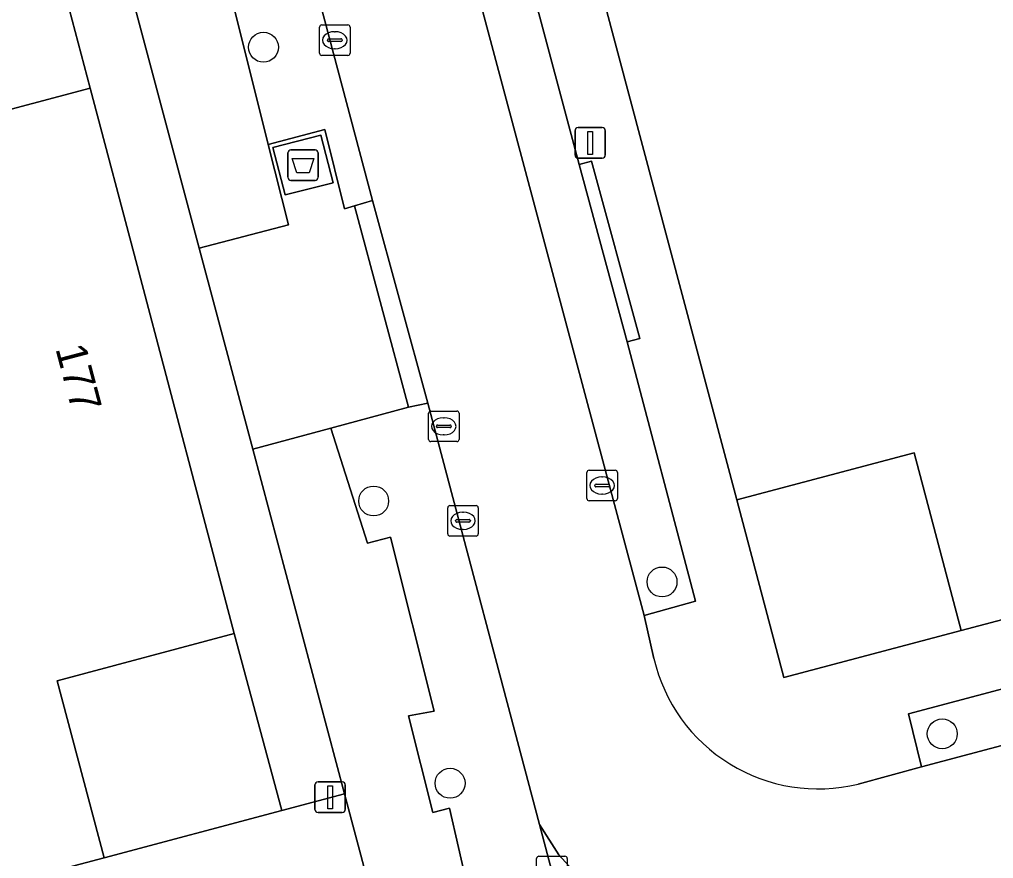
# Model space of a CAD drawing. Extents: x 162542 to 163147, y 380779 to 381521.
# Drawn here: x 162637.43 to 162669.28, y 381104.34 to 381131.79 of the extents above; entities that cross this region are included whole.
import ezdxf

# ---------------------------------------------------------------- set-up
doc = ezdxf.new("R2010")
doc.units = 0
for name, color, linetype in [('IMGEO_Afval_apart_plaats', 7, 'Continuous'), ('IMGEO_Boom', 7, 'Continuous'), ('IMGEO_Erf', 7, 'Continuous'), ('IMGEO_Groenvoorziening', 7, 'Continuous'), ('IMGEO_Kolk', 7, 'Continuous'), ('IMGEO_Lichtmast', 7, 'Continuous'), ('IMGEO_Muur', 7, 'Continuous'), ('IMGEO_Pand', 7, 'Continuous'), ('IMGEO_Pand_nummerreeks', 7, 'Continuous'), ('IMGEO_Parkeervlak_open', 7, 'Continuous'), ('IMGEO_Rijbaan_lokaal_open', 7, 'Continuous'), ('IMGEO_Rioolput', 7, 'Continuous'), ('IMGEO_Voetpad_gesloten', 7, 'Continuous'), ('IMGEO_Voetpad_open', 7, 'Continuous')]:
    doc.layers.add(name, color=color, linetype=linetype)

msp = doc.modelspace()

# ---------------------------------------------------------------- linework, layer by layer
at = {"layer": 'IMGEO_Afval_apart_plaats'}
for p, q in [((162646.209, 381126.625), (162646.209, 381127.425)), ((162646.209, 381127.425), (162646.209, 381126.625)), ((162646.309, 381127.525), (162647.099, 381127.525)), ((162647.099, 381127.525), (162646.309, 381127.525)), ((162647.199, 381127.425), (162647.199, 381126.625)), ((162647.199, 381126.625), (162647.199, 381127.425)), ((162647.099, 381126.525), (162646.309, 381126.525)), ((162646.309, 381126.525), (162647.099, 381126.525))]:
    msp.add_line(p, q, dxfattribs=at)
msp.add_lwpolyline([(162646.352, 381127.239), (162647.056, 381127.239), (162646.907, 381126.769), (162646.501, 381126.769), (162646.352, 381127.239)], dxfattribs=at)
for centre, start, end in [((162646.309, 381127.425), 90, 180), ((162646.309, 381127.425), 90, 180), ((162647.099, 381127.425), 0, 90), ((162647.099, 381127.425), 360, 90), ((162646.309, 381126.625), 180, 270), ((162646.309, 381126.625), 180, 270), ((162647.099, 381126.625), 270, 0), ((162647.099, 381126.625), 270, 0)]:
    msp.add_arc(centre, 0.1, start, end, dxfattribs=at)
at = {"layer": 'IMGEO_Boom'}
for centre in [(162645.411, 381130.88), (162649.015, 381116.036), (162658.444, 381113.388), (162667.608, 381108.419), (162651.513, 381106.802)]:
    msp.add_circle(centre, 0.489, dxfattribs=at)
at = {"layer": 'IMGEO_Erf'}
for points in [[(162639.746, 381129.54), (162636.792, 381140.677), (162633.868, 381139.932), (162635.326, 381134.447), (162636.835, 381128.769)], [(162662.432, 381110.26), (162668.23, 381111.802), (162666.685, 381117.612), (162660.887, 381116.07)], [(162646.014, 381105.912), (162644.458, 381111.704), (162638.664, 381110.158), (162640.197, 381104.368)]]:
    msp.add_lwpolyline(points, close=True, dxfattribs=at)
at = {"layer": 'IMGEO_Groenvoorziening'}
for points in [[(162646.141, 381136.563), (162644.655, 381136.184), (162645.512, 381132.926), (162644.373, 381132.48), (162645.568, 381127.699), (162647.414, 381128.192), (162648.065, 381125.594), (162648.385, 381125.691), (162648.974, 381125.871)], [(162644.655, 381136.184), (162640.435, 381135.109), (162643.311, 381124.312), (162646.229, 381125.075), (162645.568, 381127.699), (162644.373, 381132.48), (162645.512, 381132.926)], [(162650.784, 381119.239), (162650.158, 381119.106), (162647.612, 381118.42), (162648.817, 381114.655), (162649.56, 381114.853), (162650.996, 381109.159), (162650.154, 381109.01), (162650.946, 381105.841), (162651.491, 381105.99), (162652.085, 381103.415), (162653.175, 381103.613), (162653.617, 381101.793), (162655.29, 381102.237), (162654.437, 381105.453)], [(162649.56, 381114.853), (162648.817, 381114.655), (162647.612, 381118.42), (162645.063, 381117.734), (162648.066, 381106.457), (162649.592, 381100.726), (162653.617, 381101.793), (162653.175, 381103.613), (162652.085, 381103.415), (162651.491, 381105.99), (162650.946, 381105.841), (162650.154, 381109.01), (162650.996, 381109.159)]]:
    msp.add_lwpolyline(points, close=True, dxfattribs=at)
at = {"layer": 'IMGEO_Kolk'}
for p, q in [((162647.319, 381131.61), (162648.171, 381131.61)), ((162647.244, 381130.684), (162647.244, 381131.536)), ((162647.732, 381131.39), (162647.757, 381131.39)), ((162648.245, 381131.536), (162648.245, 381130.684)), ((162647.503, 381131.104), (162647.503, 381131.116)), ((162647.941, 381131.067), (162647.543, 381131.067)), ((162647.546, 381131.153), (162647.944, 381131.153)), ((162647.987, 381131.116), (162647.987, 381131.104)), ((162648.171, 381130.61), (162647.319, 381130.61)), ((162647.755, 381130.83), (162647.73, 381130.83)), ((162655.986, 381116.118), (162655.986, 381116.97)), ((162656.061, 381117.044), (162656.913, 381117.044)), ((162656.987, 381116.97), (162656.987, 381116.118)), ((162656.288, 381116.587), (162656.686, 381116.587)), ((162656.474, 381116.824), (162656.499, 381116.824)), ((162656.245, 381116.538), (162656.245, 381116.55)), ((162656.683, 381116.501), (162656.285, 381116.501)), ((162656.497, 381116.264), (162656.472, 381116.264)), ((162656.729, 381116.55), (162656.729, 381116.538)), ((162656.913, 381116.044), (162656.061, 381116.044)), ((162651.435, 381114.963), (162651.435, 381115.815)), ((162651.51, 381115.889), (162652.362, 381115.889)), ((162651.923, 381115.669), (162651.948, 381115.669)), ((162652.436, 381115.815), (162652.436, 381114.963)), ((162651.694, 381115.383), (162651.694, 381115.395)), ((162652.132, 381115.346), (162651.734, 381115.346)), ((162651.737, 381115.432), (162652.135, 381115.432)), ((162652.178, 381115.395), (162652.178, 381115.383)), ((162651.946, 381115.109), (162651.921, 381115.109)), ((162652.362, 381114.889), (162651.51, 381114.889)), ((162654.344, 381103.488), (162654.344, 381104.34)), ((162654.419, 381104.414), (162655.271, 381104.414)), ((162655.345, 381104.34), (162655.345, 381103.488))]:
    msp.add_line(p, q, dxfattribs=at)
for points in [[(162647.319, 381131.61), (162648.171, 381131.61)], [(162647.244, 381130.684), (162647.244, 381131.536)], [(162648.245, 381131.536), (162648.245, 381130.684)], [(162648.171, 381130.61), (162647.319, 381130.61)], [(162655.986, 381116.118), (162655.986, 381116.97)], [(162656.061, 381117.044), (162656.913, 381117.044)], [(162656.987, 381116.97), (162656.987, 381116.118)], [(162656.913, 381116.044), (162656.061, 381116.044)], [(162651.435, 381114.963), (162651.435, 381115.815)], [(162651.51, 381115.889), (162652.362, 381115.889)], [(162652.436, 381115.815), (162652.436, 381114.963)], [(162652.362, 381114.889), (162651.51, 381114.889)], [(162654.344, 381103.488), (162654.344, 381104.34)], [(162654.419, 381104.414), (162655.271, 381104.414)], [(162655.345, 381104.34), (162655.345, 381103.488)]]:
    msp.add_lwpolyline(points, dxfattribs=at)
for centre, radius, start, end in [((162647.321, 381131.534), 0.0765, 91.552, 178.448), ((162647.321, 381131.534), 0.0765, 91.552, 178.448), ((162648.169, 381131.534), 0.0765, 1.552, 88.448), ((162648.169, 381131.534), 0.0765, 1.552, 88.448), ((162647.543, 381131.113), 0.0403, 85.8775, 175.7526), ((162647.54, 381131.103), 0.0366, 178.938, 274.7102), ((162647.944, 381131.11), 0.043, 264.8664, 352.4533), ((162647.948, 381131.115), 0.0386, 1.7309, 96.639), ((162647.321, 381130.686), 0.0765, 181.552, 268.448), ((162647.321, 381130.686), 0.0765, 181.552, 268.448), ((162648.169, 381130.686), 0.0765, 271.552, 358.448), ((162648.169, 381130.686), 0.0765, 271.552, 358.448), ((162656.063, 381116.968), 0.0765, 91.552, 178.448), ((162656.063, 381116.968), 0.0765, 91.552, 178.448), ((162656.911, 381116.968), 0.0765, 1.552, 88.448), ((162656.911, 381116.968), 0.0765, 1.552, 88.448), ((162656.285, 381116.547), 0.0403, 85.8775, 175.7526), ((162656.69, 381116.549), 0.0386, 1.7309, 96.639), ((162656.282, 381116.537), 0.0366, 178.938, 274.7102), ((162656.686, 381116.544), 0.043, 264.8664, 352.4533), ((162656.063, 381116.12), 0.0765, 181.552, 268.448), ((162656.063, 381116.12), 0.0765, 181.552, 268.448), ((162656.911, 381116.12), 0.0765, 271.552, 358.448), ((162656.911, 381116.12), 0.0765, 271.552, 358.448), ((162651.512, 381115.813), 0.0765, 91.552, 178.448), ((162651.512, 381115.813), 0.0765, 91.552, 178.448), ((162652.36, 381115.813), 0.0765, 1.552, 88.448), ((162652.36, 381115.813), 0.0765, 1.552, 88.448), ((162651.734, 381115.392), 0.0403, 85.8775, 175.7526), ((162651.731, 381115.382), 0.0366, 178.938, 274.7102), ((162652.135, 381115.389), 0.043, 264.8664, 352.4533), ((162652.139, 381115.394), 0.0386, 1.7309, 96.639), ((162651.512, 381114.965), 0.0765, 181.552, 268.448), ((162651.512, 381114.965), 0.0765, 181.552, 268.448), ((162652.36, 381114.965), 0.0765, 271.552, 358.448), ((162652.36, 381114.965), 0.0765, 271.552, 358.448), ((162654.421, 381104.338), 0.0765, 91.552, 178.448), ((162654.421, 381104.338), 0.0765, 91.552, 178.448), ((162655.269, 381104.338), 0.0765, 1.552, 88.448), ((162655.269, 381104.338), 0.0765, 1.552, 88.448)]:
    msp.add_arc(centre, radius, start, end, dxfattribs=at)
for centre, major_axis, ratio, start_param, end_param in [((162647.731, 381131.11), (-0.387, 0.002), 0.722429, 4.712389, 7.853982), ((162647.756, 381131.11), (-0.39, 0.002), 0.717154, 1.570796, 4.712389), ((162656.473, 381116.544), (-0.387, 0.002), 0.722429, 4.712389, 7.853982), ((162656.498, 381116.544), (-0.39, 0.002), 0.717154, 1.570796, 4.712389), ((162651.922, 381115.389), (-0.387, 0.002), 0.722429, 4.712389, 7.853982), ((162651.947, 381115.389), (-0.39, 0.002), 0.717154, 1.570796, 4.712389)]:
    msp.add_ellipse(centre, major_axis=major_axis, ratio=ratio, start_param=start_param, end_param=end_param, dxfattribs=at)
at = {"layer": 'IMGEO_Lichtmast'}
for p, q in [((162655.599, 381127.352), (162655.599, 381128.152)), ((162655.599, 381128.152), (162655.599, 381127.352)), ((162655.699, 381128.252), (162656.489, 381128.252)), ((162656.489, 381128.252), (162655.699, 381128.252)), ((162656.589, 381128.152), (162656.589, 381127.352)), ((162656.589, 381127.352), (162656.589, 381128.152)), ((162656.489, 381127.252), (162655.699, 381127.252)), ((162655.699, 381127.252), (162656.489, 381127.252)), ((162647.096, 381105.946), (162647.096, 381106.746)), ((162647.096, 381106.746), (162647.096, 381105.946)), ((162647.196, 381106.846), (162647.986, 381106.846)), ((162647.986, 381106.846), (162647.196, 381106.846)), ((162648.086, 381106.746), (162648.086, 381105.946)), ((162648.086, 381105.946), (162648.086, 381106.746)), ((162647.986, 381105.846), (162647.196, 381105.846)), ((162647.196, 381105.846), (162647.986, 381105.846))]:
    msp.add_line(p, q, dxfattribs=at)
for points in [[(162656.019, 381128.127), (162656.169, 381128.127), (162656.169, 381127.377), (162656.019, 381127.377), (162656.019, 381128.127)], [(162647.516, 381106.721), (162647.666, 381106.721), (162647.666, 381105.971), (162647.516, 381105.971), (162647.516, 381106.721)]]:
    msp.add_lwpolyline(points, dxfattribs=at)
for centre, start, end in [((162655.699, 381128.152), 90, 180), ((162655.699, 381128.152), 90, 180), ((162656.489, 381128.152), 0, 90), ((162656.489, 381128.152), 360, 90), ((162655.699, 381127.352), 180, 270), ((162655.699, 381127.352), 180, 270), ((162656.489, 381127.352), 270, 0), ((162656.489, 381127.352), 270, 0), ((162647.196, 381106.746), 90, 180), ((162647.196, 381106.746), 90, 180), ((162647.986, 381106.746), 0, 90), ((162647.986, 381106.746), 360, 90), ((162647.196, 381105.946), 180, 270), ((162647.196, 381105.946), 180, 270), ((162647.986, 381105.946), 270, 0), ((162647.986, 381105.946), 270, 0)]:
    msp.add_arc(centre, 0.1, start, end, dxfattribs=at)
at = {"layer": 'IMGEO_Muur'}
for points in [[(162668.23, 381111.802), (162662.432, 381110.26), (162660.887, 381116.07)], [(162644.458, 381111.704), (162646.014, 381105.912), (162640.197, 381104.368)]]:
    msp.add_lwpolyline(points, dxfattribs=at)
at = {"layer": 'IMGEO_Pand'}
for points in [[(162684.115, 381122.206), (162684.328, 381122.262), (162682.52, 381129.057), (162682.737, 381129.114), (162681.431, 381133.908), (162681.144, 381134.962), (162680.329, 381137.953), (162679.725, 381140.171), (162676.798, 381139.397), (162668.718, 381137.261), (162659.049, 381134.67), (162656.145, 381133.899), (162657.803, 381127.667), (162660.887, 381116.07), (162666.685, 381117.612), (162668.23, 381111.802), (162680.279, 381114.986), (162678.746, 381120.787)], [(162619.323, 381124.12), (162616.078, 381123.263), (162617.623, 381117.468), (162618.478, 381114.259), (162620.529, 381106.565), (162620.756, 381106.626), (162621.054, 381105.498), (162621.283, 381105.559), (162626.635, 381106.974), (162628.178, 381101.192), (162640.197, 381104.368), (162638.664, 381110.158), (162644.458, 381111.704), (162641.278, 381123.741), (162639.746, 381129.54), (162636.835, 381128.769), (162624.265, 381125.424)]]:
    msp.add_lwpolyline(points, close=True, dxfattribs=at)
at = {"layer": 'IMGEO_Parkeervlak_open'}
for points in [[(162750.234, 381131.33), (162666.499, 381109.073), (162666.934, 381107.34), (162774.201, 381135.871), (162796.063, 381141.696), (162882.877, 381164.808), (162901.876, 381169.92), (162904.167, 381170.544), (162903.648, 381172.331), (162882.303, 381166.521), (162850.91, 381158.201), (162843.113, 381156.134), (162825.633, 381151.487), (162819.826, 381149.913), (162790.747, 381142.166), (162781.519, 381139.707), (162755.957, 381132.897)], [(162651.083, 381144.497), (162649.38, 381144.042), (162657.855, 381112.29), (162659.54, 381112.76), (162657.309, 381121.241), (162655.734, 381127.049)]]:
    msp.add_lwpolyline(points, close=True, dxfattribs=at)
at = {"layer": 'IMGEO_Rijbaan_lokaal_open'}
for points in [[(162658.181, 381110.883), (162657.855, 381112.29), (162649.38, 381144.042), (162643.686, 381165.375)], [(162641.237, 381154.972), (162643.024, 381148.328), (162645.846, 381137.677), (162646.141, 381136.563), (162648.974, 381125.871), (162650.784, 381119.239), (162654.437, 381105.453), (162655.072, 381104.461), (162655.942, 381103.505), (162657.142, 381102.572), (162658.064, 381102.039), (162660.094, 381101.266), (162661.162, 381101.085), (162663.041, 381101.13), (162667.876, 381102.415), (162673.722, 381103.968), (162674.634, 381104.211), (162692.09, 381108.85), (162694.038, 381109.357)], [(162752.751, 381124.999), (162754.693, 381125.516), (162758.591, 381126.553), (162768.331, 381129.144), (162769.49, 381129.452), (162775.451, 381131.037), (162774.201, 381135.871), (162666.934, 381107.34), (162664.853, 381106.777)]]:
    msp.add_lwpolyline(points, dxfattribs=at)
msp.add_arc((162663.543, 381112.122), 5.503, 193.012, 283.7711, dxfattribs=at)
at = {"layer": 'IMGEO_Rioolput'}
for p, q in [((162650.807, 381118.053), (162650.807, 381118.905)), ((162650.882, 381118.979), (162651.734, 381118.979)), ((162651.808, 381118.905), (162651.808, 381118.053)), ((162651.109, 381118.522), (162651.507, 381118.522)), ((162651.295, 381118.759), (162651.32, 381118.759)), ((162651.066, 381118.473), (162651.066, 381118.485)), ((162651.504, 381118.436), (162651.106, 381118.436)), ((162651.318, 381118.199), (162651.293, 381118.199)), ((162651.55, 381118.485), (162651.55, 381118.473)), ((162651.734, 381117.979), (162650.882, 381117.979))]:
    msp.add_line(p, q, dxfattribs=at)
for points in [[(162650.807, 381118.053), (162650.807, 381118.905)], [(162650.882, 381118.979), (162651.734, 381118.979)], [(162651.808, 381118.905), (162651.808, 381118.053)], [(162651.734, 381117.979), (162650.882, 381117.979)]]:
    msp.add_lwpolyline(points, dxfattribs=at)
for centre, radius, start, end in [((162650.884, 381118.903), 0.0765, 91.552, 178.448), ((162650.884, 381118.903), 0.0765, 91.552, 178.448), ((162651.732, 381118.903), 0.0765, 1.552, 88.448), ((162651.732, 381118.903), 0.0765, 1.552, 88.448), ((162651.106, 381118.482), 0.0403, 85.8775, 175.7526), ((162651.511, 381118.484), 0.0386, 1.7309, 96.639), ((162651.103, 381118.472), 0.0366, 178.938, 274.7102), ((162651.507, 381118.479), 0.043, 264.8664, 352.4533), ((162650.884, 381118.055), 0.0765, 181.552, 268.448), ((162650.884, 381118.055), 0.0765, 181.552, 268.448), ((162651.732, 381118.055), 0.0765, 271.552, 358.448), ((162651.732, 381118.055), 0.0765, 271.552, 358.448)]:
    msp.add_arc(centre, radius, start, end, dxfattribs=at)
for centre, major_axis, ratio, start_param, end_param in [((162651.294, 381118.479), (-0.387, 0.002), 0.722429, 4.712389, 7.853982), ((162651.319, 381118.479), (-0.39, 0.002), 0.717154, 1.570796, 4.712389)]:
    msp.add_ellipse(centre, major_axis=major_axis, ratio=ratio, start_param=start_param, end_param=end_param, dxfattribs=at)
at = {"layer": 'IMGEO_Voetpad_gesloten'}
msp.add_lwpolyline([(162647.292, 381128.002), (162645.722, 381127.603), (162646.117, 381126.048), (162647.687, 381126.447)], close=True, dxfattribs=at)
at = {"layer": 'IMGEO_Voetpad_open'}
for points in [[(162645.063, 381117.734), (162643.311, 381124.312), (162640.435, 381135.109), (162640.133, 381136.243), (162637.327, 381146.78), (162635.59, 381153.303), (162633.072, 381162.758), (162632.437, 381164.912), (162630.483, 381164.337), (162632.03, 381158.534), (162635.122, 381146.939), (162636.792, 381140.677), (162639.746, 381129.54), (162641.278, 381123.741), (162644.458, 381111.704), (162646.014, 381105.912), (162648.066, 381106.457)], [(162648.385, 381125.691), (162648.065, 381125.594), (162647.414, 381128.192), (162645.568, 381127.699), (162646.229, 381125.075), (162643.311, 381124.312), (162645.063, 381117.734), (162647.612, 381118.42), (162650.158, 381119.106)], [(162646.117, 381126.048), (162645.722, 381127.603), (162647.292, 381128.002), (162647.687, 381126.447)], [(162657.722, 381121.348), (162656.14, 381127.159), (162655.734, 381127.049), (162657.309, 381121.241)], [(162648.385, 381125.691), (162650.158, 381119.106), (162650.784, 381119.239), (162648.974, 381125.871)], [(162619.27, 381092.687), (162642.433, 381098.828), (162649.592, 381100.726), (162648.066, 381106.457), (162646.014, 381105.912), (162640.197, 381104.368), (162628.178, 381101.192), (162622.828, 381099.762), (162623.542, 381097.085), (162617.289, 381095.423), (162614.958, 381094.735), (162609.155, 381093.173), (162609.125, 381093.283), (162608.871, 381093.213), (162593.07, 381088.868), (162591.456, 381089.793), (162590.201, 381094.388), (162586.182, 381093.351), (162587.653, 381087.807), (162588.555, 381084.517), (162589.109, 381084.669), (162589.233, 381084.7)]]:
    msp.add_lwpolyline(points, close=True, dxfattribs=at)
for points in [[(162651.083, 381144.497), (162655.734, 381127.049)], [(162657.803, 381127.667), (162656.145, 381133.899)], [(162666.934, 381107.34), (162666.499, 381109.073), (162750.234, 381131.33)], [(162660.887, 381116.07), (162657.803, 381127.667)], [(162655.734, 381127.049), (162656.14, 381127.159), (162657.722, 381121.348), (162657.309, 381121.241)], [(162657.309, 381121.241), (162659.54, 381112.76), (162657.855, 381112.29)], [(162668.23, 381111.802), (162662.432, 381110.26), (162660.887, 381116.07)], [(162680.279, 381114.986), (162668.23, 381111.802)], [(162657.855, 381112.29), (162658.181, 381110.883)], [(162664.853, 381106.777), (162666.934, 381107.34)], [(162655.942, 381103.505), (162655.072, 381104.461), (162654.437, 381105.453), (162655.29, 381102.237)]]:
    msp.add_lwpolyline(points, dxfattribs=at)
msp.add_arc((162663.543, 381112.122), 5.503, 193.012, 283.7711, dxfattribs=at)

# ---------------------------------------------------------------- texts
at = {"layer": 'IMGEO_Pand_nummerreeks'}
msp.add_text('177', height=1, rotation=284.7984, dxfattribs=at).set_placement((162638.603, 381121.026))

doc.saveas('drawing.dxf')
